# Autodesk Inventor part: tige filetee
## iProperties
Created: 2009-03
Part Number: tige filetee
Document SubType Name: Modeling
Designer: Ordi1
Author: Ordi1
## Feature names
1. Extrusion1
2. Chanfrein1 [Chamfer]
